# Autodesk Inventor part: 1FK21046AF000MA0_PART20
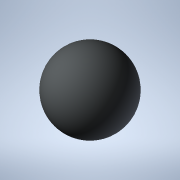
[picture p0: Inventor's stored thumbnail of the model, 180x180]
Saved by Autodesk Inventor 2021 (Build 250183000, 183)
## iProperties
Created: 2025-04
Part Number: 1FK21046AF000MA0_PART20
Material: Generic
Catalog Web Link: www.3dfindit.com
Description: -Servo synchronous motor
Document SubType Name: Modeling
Designer: psAdmin
Mass: 0.137258 g
Surface Area: 1.2868 cm^2
Volume: 0.137258 cm^3
Density: 1 g/cm^3
Appearance: PSOLRGB-212-217-219
Category: PARTsolutions
Title: 1FK21046AF000MA0_PART20
Author: Cadenas PARTsolutions
Comments: Servo synchronous motor
Sending System: PARTsolutions
Preprocessor: ST-DEVELOPER v19.3
PSOL_IDENT_0: {$CADENAS_DATA/23d-libs/siemens_ag/_cat_/1c/1f/1fk21046af000ma0.prj},216 {VTYP=3D},{NB=1FK21046AF000
PSOL_IDENT_1: MA0_PART20},{LINA=1FK21046AF000MA0_PART20},{NN=1FK21046AF000MA0_PART20},{NOPRJ=TRUE},{DATE=19.08.202
PSOL_IDENT_2: 5 14:00:28},{GEOMDATE=30.07.2025 02:02:08},{VERSION=},{LINEID=10},{WBVAR=},{WBNUMERIC=}  {NB=1FK2104
PSOL_IDENT_3: 6AF000MA0_PART20},{LINA=1FK21046AF000MA0_PART20},{KT=DUMMY},{PREVIEW=../../../_pool_/cb/72/p_d211_xx
PSOL_IDENT_4: _00434j.png},{DESCSHORT=SIMOTICS S-1FK2 HD, SINAMICS S210 3AC 400V-480V, 3.2 Nm, 3000 rpm},{DESCLONG=
PSOL_IDENT_5: SIMOTICS S-1FK2 HD servo motor M0=3.2 Nm; PN = 1 kW at nN=3000 rpm (380-480 V); PN = 0.5 kW at nN=15
PSOL_IDENT_6: 00 rpm (200-240 V); degree of protection IP64; cylindrical shaft D19x40mm; absolute encoder 22-bit +
PSOL_IDENT_7: 12-bit multiturn (encoder AM22DQC); with OCC interface; plug size M17, rotatable; SIMOTICS S-1FK2 s
PSOL_IDENT_8: ervomotorfor a wide range of uses in industrial environments. SIMOTICS S‑1FK2 servomotors are compac
PSOL_IDENT_9: t synchronous motors with a high dynamic performance that set themselves apart as a result of their
PSOL_IDENT_10: high power density, degree of protection and overload capability. The motors are available in two va
PSOL_IDENT_11: riants: as High Dynamic variant (highest dynamic performance as a result of the low intrinsic moment
PSOL_IDENT_12: of inertia for applications demanding a high dynamic performance with low moved masses) - and as Co
PSOL_IDENT_13: mpact variant (precise and stable closed-loop control for medium up to large moved masses as a resul
PSOL_IDENT_14: t of a medium intrinsic moment of inertia). SIMOTICSS‑1FK2 servomotors fully exploit their strengths
PSOL_IDENT_15: in a system with the SINAMICSS210 frequency converter and simple connection using the one cable con
PSOL_IDENT_16: nection (OCC). Advantages include the short control and positioning times, fast and precise correcti
PSOL_IDENT_17: on of disturbing quantities as well as stable control with a high dynamic performance. The servo mot
PSOL_IDENT_18: ors can be configured to address a wide range of requirements. For example with and without holding
PSOL_IDENT_19: brake, IP64 or IP65 degree of protection, singleturn or multiturn absolute encoders - to name just a
PSOL_IDENT_20: few. Further, the servomotors are available in different shaft heights extending from 20 to 100. A
PSOL_IDENT_21: shaft sealing ring is available to achieve an IP65 degree of protection and for subsequent mounting
PSOL_IDENT_22: at the motor or as spare part. SIMOTICS - the optimum motor for each and every motion control applic
PSOL_IDENT_23: ation.},{INTNO=195125049666},{SUPPLIERALTNO=1FK2104-6AF00-0MA0},{MANUID=1FK21046AF000MA0},{MANUNAME=
PSOL_IDENT_24: Siemens},{MANUTYPEDESC=Synchronous motor 1FK2-HD 3.2 NM},{AAU732=SIMOTICS},{AAO057=S-1FK2},{AAU734=S
PSOL_IDENT_25: IMOTICS S-1FK2 HD servo motor M0=3.2 Nm; PN = 1 kW at nN=3000 rpm (380-480 V); PN = 0.5 kW at nN=150
PSOL_IDENT_26: 0 rpm (200-240 V); degree of protection IP64; cylindrical shaft D19x40mm; absolute encoder 22-bit +
PSOL_IDENT_27: 12-bit multiturn (encoder AM22DQC); with OCC interface; plug size M17, rotatable;},{AAW338=Synchrono
PSOL_IDENT_28: us motor 1FK2-HD 3.2 NM},{AAO742=SIMOTICS},{AAO663=4042948694374},{NOCUPEROU=1},{PRICEQUANTITY=1},{Q
PSOL_IDENT_29: UANTITYMIN=1},{QUANTITYINT=1},{CTN=85015220},{COO=DE},{AAO676=1FK2104-6AF00-0MA0},{AAO677=Siemens AG
PSOL_IDENT_30: },{ORDERUNIT=C62},{CONTENTUNIT=C62}
NB: 1FK21046AF000MA0_PART20
NT: Servo synchronous motor
NBSYN: $MANUID._PART20
LINA: 1FK21046AF000MA0_PART20
CATALOG: SIEMENS
PREVIEW: ../../../_pool_/cb/72/p_d211_xx_00434j.png
DESCSHORT: SIMOTICS S-1FK2 HD, SINAMICS S210 3AC 400V-480V, 3.2 Nm, 3000 rpm
DESCLONG: SIMOTICS S-1FK2 HD servo motor M0=3.2 Nm; PN = 1 kW at nN=3000 rpm (380-480 V); PN = 0.5 kW at nN=1500 rpm (200-240 V); degree of protection IP64; cylindrical s
INTNO: 195125049666
SUPPLIERALTNO: 1FK2104-6AF00-0MA0
MANUID: 1FK21046AF000MA0
MANUNAME: Siemens
MANUTYPEDESC: Synchronous motor 1FK2-HD 3.2 NM
AAU732: SIMOTICS
AAO057: S-1FK2
AAU734: SIMOTICS S-1FK2 HD servo motor M0=3.2 Nm; PN = 1 kW at nN=3000 rpm (380-480 V); PN = 0.5 kW at nN=1500 rpm (200-240 V); degree of protection IP64; cylindrical s
AAW338: Synchronous motor 1FK2-HD 3.2 NM
AAO742: SIMOTICS
AAO663: 4042948694374.0
NOCUPEROU: 1
PRICEQUANTITY: 1
QUANTITYMIN: 1
QUANTITYINT: 1
CTN: 85015220
COO: DE
ARTICLENO: 1FK21046AF000MA0_PART20
BOMINFO: 1FK21046AF000MA0_PART20
CREATOR: CADENAS GmbH
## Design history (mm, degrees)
feature "2025_04_17_15_39_11_0412"
body "Solid1"
